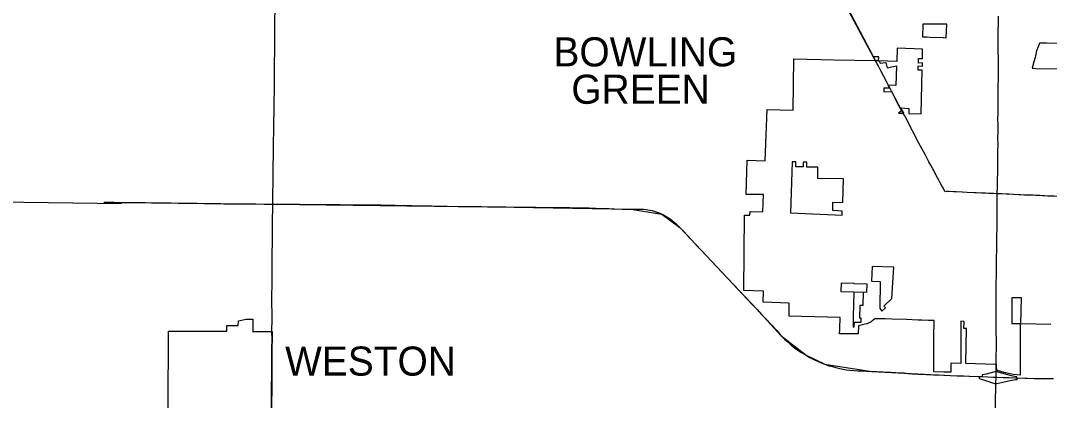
# Model space of a CAD drawing. Extents: x 0 to 851, y 0 to 440.
# Drawn here: x 229.7 to 318.5, y 193.8 to 226.5 of the extents above; entities that cross this region are included whole.
import ezdxf

# ---------------------------------------------------------------- set-up
doc = ezdxf.new("R2010")
doc.units = 0
for name, color, linetype in [('DV_X_Corp_Line', 7, 'Continuous'), ('GM_X_Corporation_Text', 7, 'Continuous'), ('GM_X_Interchange_Ramps', 7, 'Continuous'), ('GM_X_State_Route', 7, 'Continuous'), ('GM_X_US_Route', 7, 'Continuous'), ('RD_P_Fence', 7, 'Continuous')]:
    doc.layers.add(name, color=color, linetype=linetype)

msp = doc.modelspace()

# ---------------------------------------------------------------- linework, layer by layer
at = {"layer": 'DV_X_Corp_Line'}
for points in [[(318.618, 200.295), (316.035, 200.378), (316.087, 202.598), (315.264, 202.606), (315.249, 200.407), (315.984, 200.379), (315.969, 195.927), (315.364, 195.986), (314.703, 196.124), (314.203, 196.269), (314.015, 196.328), (313.925, 196.511), (313.928, 196.843), (313.827, 196.847), (311.294, 196.941), (311.339, 199.964), (311.12, 199.959), (311.129, 200.572), (310.853, 200.58), (310.84, 196.933), (309.977, 196.958), (309.981, 196.18), (309.391, 196.19), (308.513, 196.233), (308.517, 197.783), (308.535, 199.636), (308.541, 200.202), (308.545, 200.647), (308.049, 200.664), (307.478, 200.683), (307.168, 200.694), (306.156, 200.731), (304.888, 200.768), (304.332, 200.786), (303.437, 200.81), (303.289, 200.691), (303.202, 200.622), (303.105, 200.549), (303.051, 200.513), (303.003, 200.482), (302.95, 200.451), (302.901, 200.427), (302.857, 200.409), (302.792, 200.385), (302.75, 200.372), (302.7, 200.357), (302.472, 200.296), (302.02, 200.191), (302.002, 199.51), (300.384, 199.505), (300.399, 199.883), (300.395, 199.964), (300.423, 200.905), (296.034, 201.029), (296.039, 202.14), (293.8, 202.224), (293.803, 203.171), (293.785, 203.172), (292.133, 203.251), (292.19, 209.748), (292.641, 209.732), (292.652, 210.071), (293.762, 210.027), (293.804, 211.521), (292.31, 211.543), (292.409, 214.497), (293.967, 214.437), (294.125, 218.873), (296.365, 218.798), (296.43, 223.252), (299.919, 223.159), (303.497, 223.087), (303.751, 223.11), (303.76, 223.406), (303.594, 223.414), (303.326, 223.42), (301.088, 227.615)], [(319.179, 224.576), (318.247, 224.587), (317.655, 224.598), (317.537, 224.271), (317.397, 223.934), (317.26, 223.347), (317.143, 222.984), (317.01, 222.441), (317.314, 222.414), (319.328, 222.376)], [(242.423, 193.08), (242.463, 199.732), (242.683, 199.735), (246.917, 199.732), (247.479, 199.728), (247.486, 200.227), (248.48, 200.22), (248.489, 200.633), (249.157, 200.762), (249.157, 200.769), (249.74, 200.767), (249.738, 199.824), (249.736, 199.79), (249.731, 199.757), (249.717, 199.712), (251.397, 199.7), (251.383, 197.616), (251.362, 195.22), (251.341, 192.977)]]:
    msp.add_lwpolyline(points, dxfattribs=at)
for points in [[(307.54, 225.131), (307.951, 225.131), (308.192, 225.126), (309.317, 225.09), (309.353, 225.073), (309.588, 225.062), (309.638, 226.231), (307.567, 226.231)], [(307.185, 222.881), (307.188, 222.944), (307.196, 223.276), (307.542, 223.27), (307.554, 224.074), (305.347, 224.154), (305.33, 223.011), (303.78, 223.074), (303.821, 222.987), (303.882, 222.859), (304.392, 222.93), (304.502, 222.463), (305.303, 222.649), (305.244, 220.934), (304.562, 220.961), (304.698, 220.703), (304.215, 220.703), (304.215, 220.409), (304.853, 220.41), (305.144, 219.861), (305.475, 219.237), (305.742, 218.746), (305.473, 218.562), (305.944, 218.548), (305.659, 218.999), (306.352, 218.966), (306.354, 218.536), (307.414, 218.506), (307.524, 222.266), (307.161, 222.279), (307.165, 222.628), (307.531, 222.613), (307.539, 222.894)], [(296.303, 214.347), (296.16, 209.943), (300.612, 209.754), (300.619, 210.105), (299.799, 210.136), (299.806, 210.873), (300.678, 210.841), (300.71, 212.887), (298.494, 212.924), (298.505, 213.881), (297.844, 213.904), (297.553, 213.903), (297.556, 214.325), (297.248, 214.33), (297.248, 213.911), (296.609, 213.929), (296.615, 214.342)], [(303.198, 205.311), (303.154, 204.051), (303.901, 204.029), (303.857, 201.686), (304.041, 201.462), (304.348, 201.758), (304.216, 201.899), (304.901, 202.56), (305.067, 205.255)], [(300.521, 203.867), (300.502, 203.161), (302.746, 203.094), (302.77, 203.781), (301.639, 203.81), (301.64, 203.853)], [(301.554, 200.09), (301.658, 200.112), (301.662, 200.519), (302.236, 200.521), (302.239, 200.848), (302.123, 200.851), (302.148, 201.983), (302.418, 201.976), (302.459, 203.066), (301.61, 203.091), (301.558, 201.014)]]:
    msp.add_lwpolyline(points, close=True, dxfattribs=at)
at = {"layer": 'GM_X_Interchange_Ramps'}
for points in [[(312.446, 195.812), (312.442, 195.644), (312.444, 195.643), (312.633, 195.597), (313.677, 195.24), (313.791, 195.203), (313.884, 195.2)], [(313.895, 196.215), (313.797, 196.218), (313.659, 196.179), (313.052, 196.023), (312.883, 195.983), (312.74, 195.957), (312.705, 195.954), (312.696, 195.804)], [(313.884, 195.2), (313.958, 195.199), (314.483, 195.321), (315.219, 195.492), (315.438, 195.536), (315.576, 195.554), (315.706, 195.561), (315.709, 195.701)], [(315.688, 195.702), (315.69, 195.792), (315.66, 195.794), (315.517, 195.814), (315.349, 195.847), (315.231, 195.88), (314.071, 196.196), (314.008, 196.21), (313.965, 196.214), (313.895, 196.215)]]:
    msp.add_lwpolyline(points, dxfattribs=at)
at = {"layer": 'GM_X_State_Route'}
for points in [[(251.387, 199.829), (251.395, 200.669), (251.392, 201.503), (251.387, 201.899), (251.377, 202.168), (251.379, 202.453), (251.382, 202.842), (251.394, 203.697), (251.399, 204.367), (251.406, 205.236), (251.415, 206.406), (251.428, 207.416), (251.433, 208.502), (251.441, 209.485), (251.448, 210.199), (251.459, 210.699), (251.467, 211.675), (251.483, 212.493), (251.479, 212.974), (251.486, 213.529), (251.494, 214.127), (251.507, 214.796), (251.513, 215.14), (251.518, 215.38), (251.526, 216.123), (251.539, 216.949), (251.552, 217.783), (251.569, 218.733), (251.581, 219.661), (251.589, 220.414), (251.595, 221.314), (251.601, 222.121), (251.612, 222.991), (251.618, 223.778), (251.629, 224.662), (251.633, 225.539), (251.638, 226.413), (251.65, 227.606)], [(301.768, 226.305), (301.532, 226.708)], [(314.081, 225.01), (314.1, 226.925)], [(302.814, 224.343), (302.796, 224.376), (302.409, 225.109), (301.962, 225.976), (301.768, 226.305)], [(314.092, 222.249), (314.08, 224.927), (314.081, 225.01)], [(302.989, 224.033), (302.814, 224.343)], [(303.362, 223.325), (303.266, 223.515), (303.107, 223.823), (302.989, 224.033)], [(303.443, 223.167), (303.362, 223.325)], [(303.525, 223.009), (303.517, 223.024), (303.513, 223.032), (303.508, 223.04), (303.506, 223.045), (303.506, 223.045), (303.504, 223.048), (303.503, 223.05), (303.485, 223.085), (303.443, 223.167)], [(304.682, 220.803), (304.646, 220.872), (304.426, 221.299), (303.972, 222.164), (303.719, 222.655), (303.641, 222.799), (303.626, 222.826), (303.526, 223.008), (303.525, 223.009)], [(314.087, 220.91), (314.093, 221.541), (314.095, 221.562), (314.092, 222.249)], [(305.757, 218.756), (305.693, 218.887), (305.497, 219.246), (305.181, 219.847), (304.869, 220.446), (304.682, 220.803)], [(314.059, 218.144), (314.062, 218.417), (314.082, 220.377), (314.087, 220.91)], [(305.835, 218.596), (305.757, 218.756)], [(308.852, 212.958), (308.706, 213.23), (308.513, 213.605), (308.441, 213.736), (308.251, 214.065), (308.1, 214.359), (307.98, 214.594), (307.77, 214.99), (307.375, 215.713), (307.097, 216.233), (306.915, 216.582), (306.479, 217.394), (306.236, 217.888), (306.005, 218.315), (305.835, 218.596)], [(314.053, 214.537), (314.055, 214.602), (314.05, 215.305), (314.062, 215.866), (314.059, 216.328), (314.058, 216.415), (314.068, 216.903), (314.065, 217.451), (314.059, 218.144)], [(314.038, 213.371), (314.042, 213.579), (314.042, 213.726), (314.041, 214.096), (314.053, 214.537)], [(313.991, 211.526), (313.99, 211.6), (314.004, 212.258), (314.006, 212.37), (314.018, 212.724), (314.028, 212.849), (314.038, 213.371)], [(309.586, 211.78), (309.499, 211.775), (309.27, 212.182), (309.208, 212.28), (309.08, 212.533), (308.885, 212.897), (308.852, 212.958)], [(310.967, 211.726), (310.46, 211.756), (310.218, 211.764), (309.834, 211.782), (309.659, 211.784), (309.586, 211.78)], [(312.781, 211.646), (312.74, 211.648), (312.664, 211.65), (312.173, 211.671), (312.045, 211.676), (311.403, 211.701), (310.967, 211.726)], [(313.299, 211.626), (313.269, 211.628), (312.996, 211.639), (312.866, 211.643), (312.781, 211.646)], [(313.99, 211.6), (313.675, 211.611), (313.45, 211.617), (313.299, 211.626)], [(313.981, 209.387), (313.994, 209.892), (314, 210.492), (313.991, 211.526)], [(314.865, 211.563), (314.778, 211.57), (314.387, 211.587), (313.99, 211.6)], [(316.36, 211.483), (316.335, 211.483), (316, 211.501), (315.871, 211.503), (315.395, 211.532), (315.006, 211.551), (314.865, 211.563)], [(316.801, 211.472), (316.774, 211.473), (316.36, 211.483)], [(318.102, 211.412), (317.969, 211.419), (317.888, 211.424), (317.668, 211.437), (317.446, 211.448), (317.329, 211.452), (317.111, 211.46), (316.809, 211.471), (316.801, 211.472)], [(322.429, 211.271), (322.305, 211.274), (321.808, 211.274), (321.099, 211.309), (320.477, 211.328), (320.12, 211.334), (319.865, 211.341), (319.488, 211.353), (319.218, 211.363), (318.914, 211.373), (318.697, 211.383), (318.359, 211.397), (318.102, 211.412)], [(313.933, 205.051), (313.937, 205.651), (313.938, 205.748), (313.943, 206.141), (313.952, 206.653), (313.956, 206.844), (313.958, 207.155), (313.964, 207.672), (313.972, 208.033), (313.981, 208.545), (313.983, 208.693), (313.981, 209.387)], [(313.897, 200.592), (313.901, 203.51), (313.932, 204.88), (313.933, 205.051)], [(313.907, 199.727), (313.898, 200.447), (313.897, 200.503), (313.897, 200.592)], [(251.33, 192.989), (251.334, 193.742), (251.355, 194.493), (251.355, 195.222), (251.359, 195.597), (251.361, 196.411), (251.367, 197.302), (251.381, 198.221), (251.39, 199.023), (251.386, 199.663), (251.387, 199.829)], [(313.901, 196.936), (313.919, 198.884), (313.907, 199.727)], [(313.893, 195.937), (313.895, 196.215), (313.898, 196.576)], [(313.898, 196.576), (313.899, 196.666)], [(313.899, 196.666), (313.901, 196.936)], [(313.703, 187.487), (313.813, 191.603), (313.884, 195.2), (313.891, 195.752)], [(313.891, 195.752), (313.893, 195.937)]]:
    msp.add_lwpolyline(points, dxfattribs=at)
at = {"layer": 'GM_X_US_Route'}
for points in [[(199.601, 211.573), (207.497, 211.109), (208.225, 211.096), (209.007, 211.093), (209.947, 211.085), (210.703, 211.089), (211.152, 211.094), (211.732, 211.091), (212.442, 211.085), (213.195, 211.075), (213.812, 211.068), (214.492, 211.059), (215.202, 211.057), (238.396, 210.754)], [(236.866, 210.866), (236.868, 210.866), (237.191, 210.863), (237.768, 210.855), (238.397, 210.849), (239.098, 210.848), (239.734, 210.835), (240.458, 210.826), (240.974, 210.817), (241.701, 210.812), (242.317, 210.806), (242.506, 210.807)], [(242.506, 210.807), (242.672, 210.808), (243.282, 210.793), (243.908, 210.787), (244.417, 210.775), (244.93, 210.769), (245.523, 210.762), (246.136, 210.751), (246.648, 210.746), (246.984, 210.74), (247.234, 210.735), (247.831, 210.731), (248.397, 210.725), (248.889, 210.721), (249.402, 210.719), (250.005, 210.712), (250.752, 210.708), (251.459, 210.699)], [(251.459, 210.699), (251.934, 210.695), (252.454, 210.687), (252.852, 210.688), (253.305, 210.687), (253.784, 210.683), (254.266, 210.676), (254.772, 210.671), (255.298, 210.673), (255.814, 210.668), (256.296, 210.66), (256.762, 210.66), (257.275, 210.658), (257.804, 210.65), (258.246, 210.65), (258.715, 210.649), (259.191, 210.639), (259.811, 210.642), (260.384, 210.635), (260.812, 210.626), (261.435, 210.615), (262.008, 210.602), (262.668, 210.591), (263.435, 210.574), (264.047, 210.563), (264.694, 210.552), (265.19, 210.544), (265.836, 210.533), (266.496, 210.518), (267.45, 210.503), (268.199, 210.49), (268.848, 210.489), (269.479, 210.492), (270.062, 210.473), (270.847, 210.467), (271.612, 210.458), (272.302, 210.444), (272.973, 210.436), (273.587, 210.433), (273.828, 210.429), (274.197, 210.423), (275.002, 210.414), (275.757, 210.405), (276.341, 210.406), (277.065, 210.394), (277.699, 210.39), (278.25, 210.382), (278.762, 210.377), (279.329, 210.351), (279.919, 210.331), (280.475, 210.319), (280.951, 210.301), (281.592, 210.278), (282.353, 210.272), (282.837, 210.264), (282.838, 210.264)], [(282.838, 210.264), (283.004, 210.262), (283.463, 210.254), (283.691, 210.237), (283.982, 210.189), (284.216, 210.145), (284.456, 210.07), (284.687, 209.989), (284.966, 209.877), (285.05, 209.838)], [(285.05, 209.838), (285.052, 209.837), (285.129, 209.801), (285.173, 209.78), (285.422, 209.642), (285.675, 209.48), (285.907, 209.318), (286.115, 209.147), (286.343, 208.942), (286.608, 208.682), (286.931, 208.331), (287.217, 208.021), (287.626, 207.588), (288.131, 207.053), (288.526, 206.627), (288.892, 206.235), (289.377, 205.726), (289.826, 205.246), (290.248, 204.792), (290.716, 204.301), (291.151, 203.837), (291.557, 203.408), (291.979, 202.961), (292.421, 202.49), (292.843, 202.037), (293.258, 201.6), (293.657, 201.171), (294.083, 200.724), (294.498, 200.281), (294.957, 199.793), (295.323, 199.362), (295.6, 199.065)], [(295.6, 199.065), (295.661, 199), (295.907, 198.804), (296.204, 198.515), (296.482, 198.292), (296.793, 198.077), (297.106, 197.888), (297.498, 197.65), (297.83, 197.459), (298.16, 197.29), (298.469, 197.147), (298.809, 197), (299.106, 196.891), (299.499, 196.747), (299.78, 196.672), (300.07, 196.59), (300.408, 196.511), (300.705, 196.456), (300.986, 196.404), (301.284, 196.366), (301.609, 196.34), (301.961, 196.311), (302.33, 196.302), (302.702, 196.286), (303.168, 196.261), (303.594, 196.244), (304.15, 196.215), (304.814, 196.194), (305.253, 196.174), (305.685, 196.147), (305.96, 196.125), (306.295, 196.09), (306.64, 196.057), (306.938, 196.039), (307.196, 196.025), (307.443, 196.018), (307.446, 196.018)], [(307.446, 196.018), (307.471, 196.017), (307.897, 195.997), (308.49, 195.967), (308.959, 195.949), (309.439, 195.935), (309.972, 195.916), (310.535, 195.887), (311.118, 195.864), (311.604, 195.843), (312.446, 195.812), (312.696, 195.804), (313.18, 195.774), (313.639, 195.76), (313.891, 195.752)], [(313.891, 195.752), (314.518, 195.736), (314.984, 195.728), (315.688, 195.702), (315.709, 195.701), (316.573, 195.669), (317.186, 195.649), (317.682, 195.631), (318.031, 195.625), (318.457, 195.635), (318.84, 195.642)]]:
    msp.add_lwpolyline(points, dxfattribs=at)
at = {"layer": 'RD_P_Fence'}
for points in [[(303.526, 223.008), (298.645, 232.097), (296.021, 237.262), (292.978, 246.851), (293.176, 257.435), (292.422, 258.899)], [(251.459, 210.699), (272.302, 210.444), (282.353, 210.272), (285.05, 209.838), (286.608, 208.682), (290.716, 204.301), (293.258, 201.6), (295.323, 199.362), (297.498, 197.65), (299.106, 196.891), (303.168, 196.261), (309.972, 195.916), (317.186, 195.649), (318.84, 195.642)]]:
    msp.add_lwpolyline(points, dxfattribs=at)

# ---------------------------------------------------------------- texts
at = {"layer": 'GM_X_Corporation_Text'}
for s, p in [('BOWLING', (275.683, 222.591)), ('GREEN', (277.228, 219.364)), ('WESTON', (252.517, 195.891))]:
    msp.add_text(s, height=2.5126, rotation=0.00001, dxfattribs=at).set_placement(p)

doc.saveas('drawing.dxf')
